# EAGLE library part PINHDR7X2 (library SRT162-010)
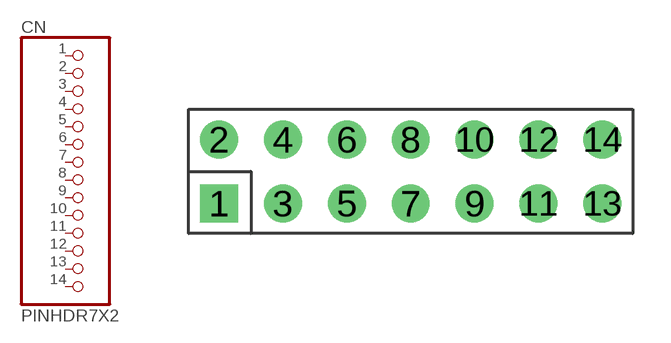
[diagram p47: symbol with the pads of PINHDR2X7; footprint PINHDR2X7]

Designator prefix CN

## PINHDR7X2  [PINHDR2X7]
1  1  pas
2  2  pas
3  3  pas
4  4  pas
5  5  pas
6  6  pas
7  7  pas
8  8  pas
9  9  pas
10  10  pas
11  11  pas
12  12  pas
13  13  pas
14  14  pas

## Footprint PINHDR2X7 (pad centres in mm)
drill 1 square: 1 -7.62,-1.27
drill 1 round: 2 -7.62,1.27; 3 -5.08,-1.27; 4 -5.08,1.27; 5 -2.54,-1.27; 6 -2.54,1.27; 7 0,-1.27; 8 0,1.27; 9 2.54,-1.27; 10 2.54,1.27; 11 5.08,-1.27; 12 5.08,1.27; 13 7.62,-1.27; 14 7.62,1.27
